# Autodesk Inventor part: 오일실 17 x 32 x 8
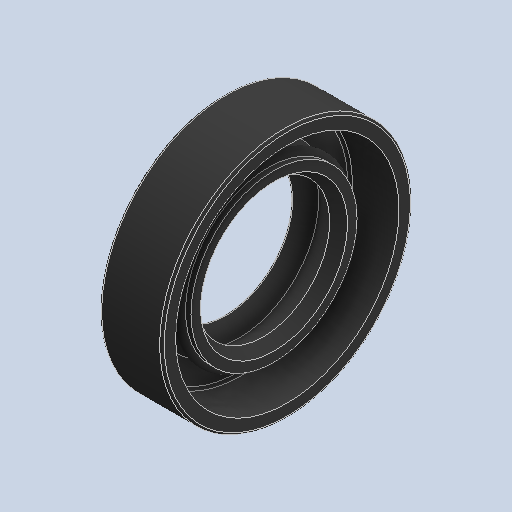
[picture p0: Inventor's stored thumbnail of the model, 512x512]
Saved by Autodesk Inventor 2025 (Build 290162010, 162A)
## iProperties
Created: 2024-07
Part Number: 오일실 17 x 32 x 8
Material: 고무
Description: 오일-실
Document SubType Name: Modeling
Designer: 학생
Density: 0.93 g/cm^3
Appearance: 기본값
Author: jhkim
Sending System: Autodesk Inventor 2025
Preprocessor: ST-DEVELOPER v20
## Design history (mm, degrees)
feature "Solid1"
node "솔리드1"
